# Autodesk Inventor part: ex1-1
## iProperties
Shininess: 64.0
Length Units: 11272
Angle Units: 11279
Time Units: 11290
Mass Units: 11286
Length Display Precision: 3
Angle Display Precision: 2
Compacted: True
Part Number: ex1-1
Document SubType Name: Modeling
Created: 2002-09
Designer: Elise Moss
Density: 0.0
Volumn: 0.0
Area: 0.0
PropertySet Name: Model Information
Control State: 0
Master: False
Checked Out: False
Author: Elise Moss
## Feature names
1. Extrusion1
